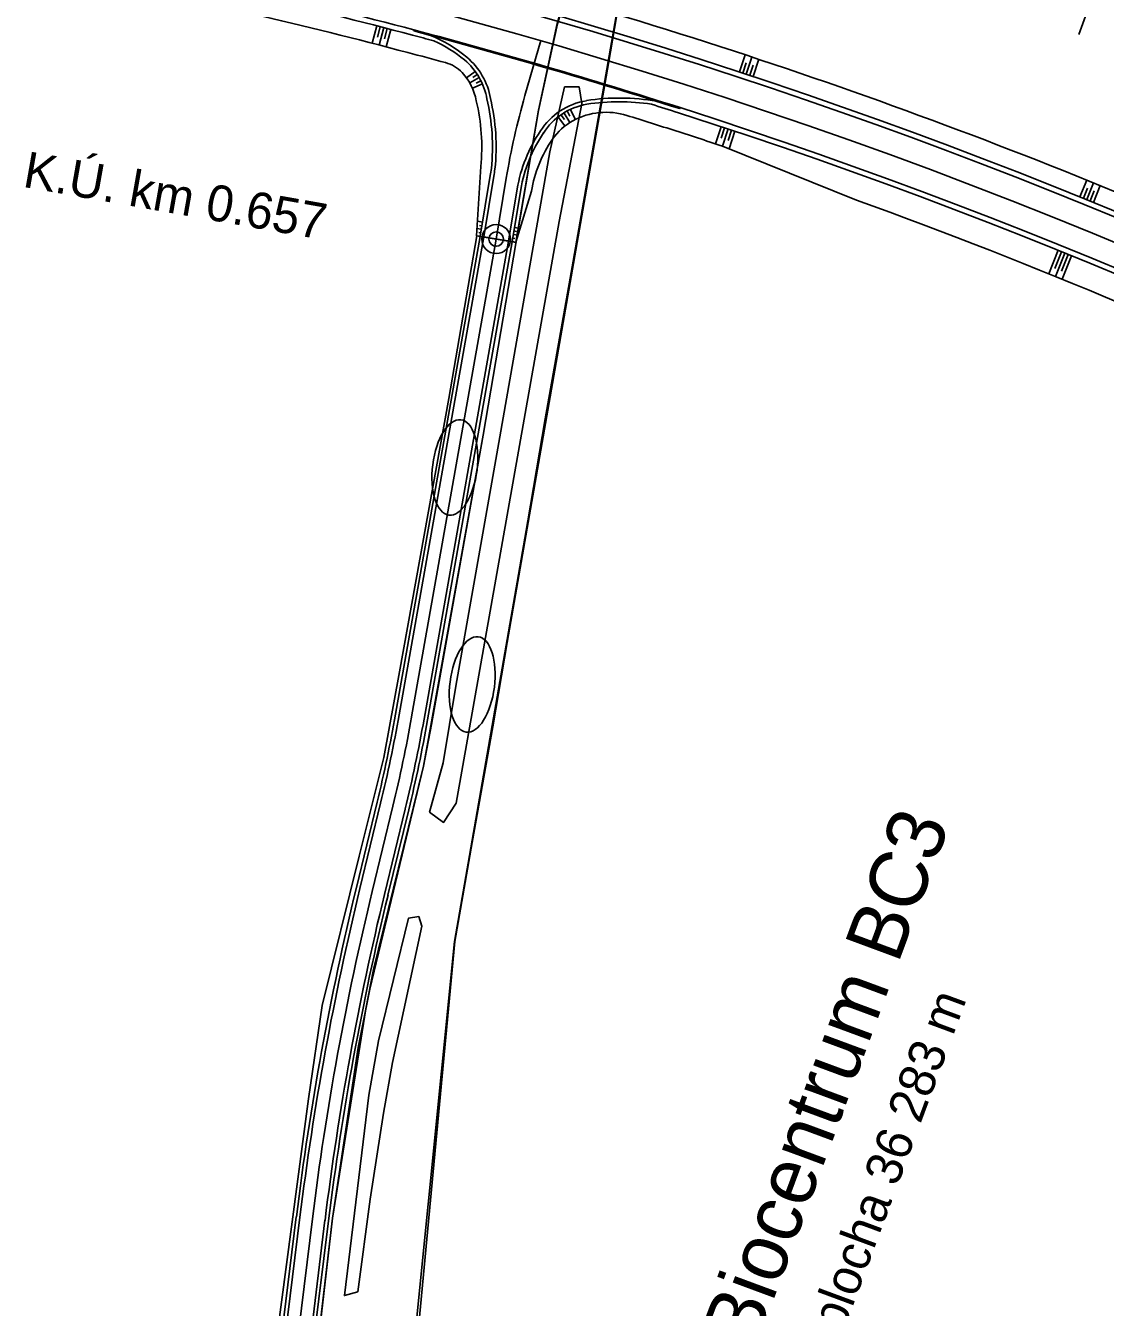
# Model space of a CAD drawing. Extents: x -552278 to -547230, y -1151007 to -1148251.
# Drawn here: x -550919.4 to -550769.8, y -1148997.3 to -1148819.7 of the extents above; entities that cross this region are included whole.
import ezdxf

# ---------------------------------------------------------------- set-up
doc = ezdxf.new("R2010")
doc.units = 0
for name, color, linetype in [('u_IP17', 7, 'Continuous'), ('u_IP17_srafa', 7, 'Continuous'), ('u_ořez_na_hlavu', 7, 'Continuous'), ('u_parcely dotčené stavbou', 7, 'Continuous'), ('u_popis', 7, 'Continuous'), ('u_STAVENIŠTĚ', 7, 'Continuous'), ('u_trat navrh', 7, 'Continuous'), ('u_VC8_cesta', 7, 'Continuous'), ('u_VC8_osa', 7, 'Continuous'), ('u_VC8_rezy_popis', 7, 'Continuous')]:
    doc.layers.add(name, color=color, linetype=linetype)

msp = doc.modelspace()

# ---------------------------------------------------------------- linework, layer by layer
at = {"layer": 'u_IP17'}
for points in [[(-550837.83, -1148795.62), (-550839.44, -1148801.11), (-550842.12, -1148807.69), (-550845.72, -1148819.42), (-550848.32, -1148831.42), (-550855.99, -1148876.44), (-550864.24, -1148922.29), (-550871.71, -1148953.2), (-550873.29, -1148961.31), (-550876.86, -1148984.92), (-550879.01, -1149003.49), (-550880.48, -1149016.26), (-550880.39, -1149028.48), (-550877.44, -1149050.4), (-550875.79, -1149066.52), (-550875.6, -1149089.61), (-550875.41, -1149112.7), (-550874.82, -1149156.2), (-550874.24, -1149199.69), (-550873.8, -1149233.1)], [(-550837.83, -1148795.62), (-550836, -1148800.28), (-550836.49, -1148812.22), (-550840.86, -1148837.25), (-550847.41, -1148874.18), (-550854.67, -1148916.87), (-550859.95, -1148946.62), (-550865.43, -1149000.99), (-550867.06, -1149034.41), (-550867.87, -1149048.76), (-550869.33, -1149071.89)]]:
    msp.add_lwpolyline(points, dxfattribs=at)
at = {"layer": 'u_IP17_srafa'}
msp.add_lwpolyline([(-550865.43, -1149000.99), (-550859.95, -1148946.62), (-550844.14, -1148855.72), (-550836.49, -1148812.22), (-550836, -1148800.28), (-550837.83, -1148795.62), (-550839.44, -1148801.11), (-550842.12, -1148807.69), (-550845.72, -1148819.42), (-550848.32, -1148831.42), (-550852.16, -1148853.93), (-550855.99, -1148876.44), (-550863.13, -1148916.53), (-550864.24, -1148922.29), (-550867.71, -1148936.4), (-550871.19, -1148950.5), (-550872.24, -1148955.91), (-550876.86, -1148984.92), (-550880.48, -1149016.26)], dxfattribs=at)
at = {"layer": 'u_ořez_na_hlavu'}
for points in [[(-550842.68, -1148828.16), (-550844.72, -1148828.18), (-550846.77, -1148837.16), (-550853.68, -1148876.67), (-550859.8, -1148911.2), (-550861.52, -1148921.83), (-550863.41, -1148928.66), (-550861.47, -1148930.1), (-550859.71, -1148927.45), (-550845.47, -1148846.81), (-550842.34, -1148830.49)], [(-550864.88, -1148943.12), (-550866.33, -1148943.35), (-550870.47, -1148960.38), (-550871.81, -1148967.88), (-550875.2, -1148995.66), (-550873.37, -1148995.13), (-550871.64, -1148982.33), (-550869.8, -1148970.41), (-550868.56, -1148963.37), (-550864.47, -1148944.46)]]:
    msp.add_lwpolyline(points, close=True, dxfattribs=at)
at = {"layer": 'u_parcely dotčené stavbou'}
for centre in [(-550859.91, -1148880.91), (-550857.51, -1148910.98)]:
    msp.add_ellipse(centre, major_axis=(0.83, 6.61), ratio=0.464088, dxfattribs=at)
at = {"layer": 'u_popis'}
for radius in [2, 1]:
    msp.add_circle((-550854.19, -1148849.26), radius, dxfattribs=at)
at = {"layer": 'u_STAVENIŠTĚ'}
msp.add_lwpolyline([(-550886.26, -1149014.34), (-550880.18, -1148968.42), (-550878.27, -1148955.49), (-550873.17, -1148934.79), (-550869.77, -1148921.11), (-550867.6, -1148909.22), (-550860.75, -1148871.36), (-550856.87, -1148848.79), (-550851.48, -1148849.7), (-550848.6, -1148833), (-550848.33, -1148831.4), (-550845.75, -1148819.38), (-550842.19, -1148807.49), (-550839.61, -1148801.16), (-550837.83, -1148795.62), (-550836, -1148800.28), (-550836.48, -1148812.21), (-550838.63, -1148824.91), (-550859.92, -1148946.62), (-550865.06, -1149001.1)], dxfattribs=at)
at = {"layer": 'u_trat navrh'}
for p, q in [((-550770.32, -1148812.12), (-550773.48, -1148820.89)), ((-550870.74, -1148819.7), (-550871.36, -1148822.12)), ((-550870.25, -1148819.83), (-550870.63, -1148821.28)), ((-550869.77, -1148819.95), (-550870.4, -1148822.37)), ((-550869.29, -1148820.08), (-550869.66, -1148821.53)), ((-550868.8, -1148820.2), (-550869.43, -1148822.62)), ((-550865.58, -1148820.27), (-550865.62, -1148820.42)), ((-550820.51, -1148826.09), (-550819.72, -1148823.72)), ((-550819.56, -1148826.41), (-550818.77, -1148824.03)), ((-550857.09, -1148826.03), (-550858.3, -1148826.92)), ((-550820.03, -1148826.25), (-550819.56, -1148824.83)), ((-550819.08, -1148826.56), (-550818.61, -1148825.14)), ((-550818.61, -1148826.72), (-550817.82, -1148824.35)), ((-550856.55, -1148826.87), (-550857.85, -1148827.62)), ((-550856.1, -1148827.76), (-550857.47, -1148828.36)), ((-550856.81, -1148826.44), (-550857.43, -1148826.85)), ((-550856.31, -1148827.31), (-550856.98, -1148827.65)), ((-550843.88, -1148831.35), (-550843.22, -1148832.7)), ((-550828.73, -1148831.04), (-550828.78, -1148831.19)), ((-550845.58, -1148832.39), (-550844.67, -1148833.58)), ((-550845.18, -1148832.1), (-550844.75, -1148832.71)), ((-550844.76, -1148831.82), (-550843.97, -1148833.1)), ((-550844.32, -1148831.57), (-550843.97, -1148832.23)), ((-550823.02, -1148833.69), (-550823.8, -1148836.06)), ((-550822.55, -1148833.84), (-550823.02, -1148835.27)), ((-550822.07, -1148834), (-550822.86, -1148836.37)), ((-550821.6, -1148834.16), (-550822.07, -1148835.58)), ((-550821.12, -1148834.32), (-550821.93, -1148836.75)), ((-550856.91, -1148848.81), (-550856.33, -1148839.22)), ((-550855.02, -1148840.46), (-550856.41, -1148848.88)), ((-550854.53, -1148840.54), (-550855.92, -1148848.96)), ((-550773.33, -1148843.41), (-550772.39, -1148841.09)), ((-550772.4, -1148843.79), (-550771.46, -1148841.47)), ((-550771.47, -1148844.17), (-550770.53, -1148841.85)), ((-550852.47, -1148849.55), (-550851.27, -1148842.32)), ((-550851.97, -1148849.64), (-550850.78, -1148842.4)), ((-550851.48, -1148849.7), (-550849.3, -1148842.64)), ((-550772.86, -1148843.6), (-550772.3, -1148842.21)), ((-550771.94, -1148843.98), (-550771.37, -1148842.59)), ((-550856.09, -1148846.92), (-550856.79, -1148846.8)), ((-550856.17, -1148847.41), (-550856.49, -1148847.36)), ((-550856.41, -1148848.89), (-550856.91, -1148848.81)), ((-550856.25, -1148847.9), (-550856.85, -1148847.81)), ((-550856.33, -1148848.4), (-550856.6, -1148848.35)), ((-550855.92, -1148848.97), (-550856.41, -1148848.89)), ((-550855.92, -1148848.97), (-550852.45, -1148849.56)), ((-550851.89, -1148849.13), (-550851.61, -1148849.18)), ((-550851.81, -1148848.64), (-550851.18, -1148848.74)), ((-550851.73, -1148848.14), (-550851.38, -1148848.2)), ((-550851.65, -1148847.65), (-550850.88, -1148847.78)), ((-550852.47, -1148849.55), (-550851.97, -1148849.64)), ((-550851.97, -1148849.64), (-550851.48, -1148849.72)), ((-550776.34, -1148850.82), (-550777.66, -1148854.07)), ((-550775.88, -1148851.01), (-550776.82, -1148853.33)), ((-550775.42, -1148851.2), (-550776.74, -1148854.44)), ((-550774.95, -1148851.39), (-550775.9, -1148853.7)), ((-550774.49, -1148851.58), (-550775.81, -1148854.82))]:
    msp.add_line(p, q, dxfattribs=at)
for points in [[(-550848.01, -1148821.73), (-550850.21, -1148829.38)], [(-550804.3, -1148843.86), (-550822.86, -1148836.37)], [(-550852.8, -1148840.82), (-550854.19, -1148849.26)]]:
    msp.add_lwpolyline(points, dxfattribs=at)
for centre, radius, start, end in [((-551056.59, -1149542.18), 756.5, 67.46341, 76.89047), ((-551056.59, -1149542.18), 754, 51.79075, 76.89047), ((-551056.59, -1149542.18), 753.25, 51.79075, 76.89047), ((-551056.59, -1149542.18), 750, 47.42068, 76.89047), ((-551056.59, -1149542.18), 746.75, 75.17971, 76.89047), ((-551056.59, -1149542.18), 746, 75.17971, 76.89047), ((-551056.59, -1149542.18), 743.5, 75.17971, 76.89047), ((-551056.59, -1149542.18), 746.6, 72.23343, 75.17971), ((-551056.59, -1149542.18), 746.75, 72.23343, 75.17971), ((-551056.59, -1149542.18), 746, 74.94401, 75.17971), ((-550870.44, -1148838.64), 19, 50.1193, 67.8822), ((-550870.44, -1148838.64), 18.5, 50.1193, 65.6311), ((-551056.59, -1149542.18), 743.5, 74.76534, 75.17971), ((-550864.35, -1148831.35), 9.5, 9.5753, 50.1193), ((-550862.53, -1148829.63), 5, 43.3915, 74.7653), ((-550864.35, -1148831.35), 9, 9.5753, 50.1193), ((-550864.35, -1148831.35), 7.5, 9.5753, 43.3915), ((-550754.13, -1148857.1), 100, 163.9042, 170.6327), ((-550883.19, -1148836.47), 27, 354.156, 13.653), ((-550883.19, -1148836.47), 28.49, 353.9415, 13.4385), ((-550883.19, -1148836.47), 28.99, 353.8749, 13.3719), ((-550840.19, -1148839.27), 9.31, 99.3246, 147.593), ((-550840.19, -1148839.27), 8.81, 99.4372, 147.7056), ((-550837.09, -1148858.72), 29.01, 79.8644, 99.1351), ((-550837.15, -1148859.63), 29.4, 81.2607, 98.7657), ((-551056.59, -1149542.18), 746, 72.23343, 72.53372), ((-551056.59, -1149542.18), 746.75, 47.42068, 72.23343), ((-550839.79, -1148839.93), 8, 118.1201, 145.6231), ((-550838.95, -1148841.49), 9.8, 75.7474, 121.0829), ((-551056.59, -1149542.18), 743.5, 72.23343, 72.78451), ((-551056.59, -1149542.18), 746, 47.42068, 72.23343), ((-550831.54, -1148845.57), 20, 145.6231, 170.6327), ((-550831.54, -1148845.57), 19.5, 145.6231, 170.6327), ((-551056.59, -1149542.18), 743.5, 71.67718, 72.23343), ((-550831.54, -1148845.57), 18, 145.6231, 170.6327), ((-550754.13, -1148857.1), 102.25, 170.0783, 170.6327), ((-550754.13, -1148857.1), 101.75, 170.0783, 170.6327), ((-551056.59, -1149542.18), 742.5, 64.03774, 70.13589)]:
    msp.add_arc(centre, radius, start, end, dxfattribs=at)
at = {"layer": 'u_VC8_cesta'}
for p, q in [((-550868.12, -1148915.1), (-550856.41, -1148848.89)), ((-550867.63, -1148915.19), (-550855.92, -1148848.97)), ((-550856.41, -1148848.89), (-550851.97, -1148849.64)), ((-550864.18, -1148915.8), (-550852.47, -1148849.55)), ((-550863.69, -1148915.89), (-550851.97, -1148849.64)), ((-550873.55, -1148939.13), (-550870.68, -1148927.29)), ((-550873.06, -1148939.24), (-550870.19, -1148927.41)), ((-550869.66, -1148940.07), (-550866.79, -1148928.24)), ((-550869.18, -1148940.19), (-550866.3, -1148928.36)), ((-550885.66, -1149015.52), (-550881.87, -1148984.75)), ((-550885.17, -1149015.58), (-550881.37, -1148984.81)), ((-550881.69, -1149016.01), (-550877.9, -1148985.24)), ((-550881.2, -1149016.07), (-550877.4, -1148985.3))]:
    msp.add_line(p, q, dxfattribs=at)
for centre, radius, start, end in [((-551062.85, -1148880.66), 197.75, 346.36, 349.9702), ((-551062.85, -1148880.66), 198.25, 346.36, 349.9702), ((-551062.85, -1148880.66), 201.75, 346.36, 349.9702), ((-551062.85, -1148880.66), 202.25, 346.36, 349.9702), ((-550482.64, -1149033.99), 402.25, 166.36, 172.9692), ((-550482.64, -1149033.99), 401.75, 166.36, 172.9692), ((-550482.64, -1149033.99), 398.25, 166.36, 172.9692), ((-550482.64, -1149033.99), 397.75, 166.36, 172.9692)]:
    msp.add_arc(centre, radius, start, end, dxfattribs=at)
at = {"layer": 'u_VC8_osa'}
for points in [[(-550865.91, -1148915.49), (-550854.19, -1148849.26)], [(-550871.36, -1148939.66), (-550868.49, -1148927.83)], [(-550883.43, -1149015.8), (-550879.64, -1148985.02)]]:
    msp.add_lwpolyline(points, dxfattribs=at)
for centre, radius, start, end in [((-551062.85, -1148880.66), 200, 346.36, 349.9702), ((-550482.64, -1149033.99), 400, 166.36, 172.9692)]:
    msp.add_arc(centre, radius, start, end, dxfattribs=at)

# ---------------------------------------------------------------- texts
at = {"layer": 'u_popis'}
for s, height, p in [('SO 09-Biocentrum BC3', 8, (-550830.17, -1149035.13)), ('celk.plocha 36 283 m ', 5, (-550810.95, -1149013.81))]:
    msp.add_text(s, height=height, rotation=69.6654, dxfattribs=at).set_placement(p)
at = {"layer": 'u_VC8_rezy_popis'}
msp.add_text('K.Ú. km 0.657 ', height=5, rotation=349.9702, dxfattribs=at).set_placement((-550919.9, -1148842))

doc.saveas('drawing.dxf')
